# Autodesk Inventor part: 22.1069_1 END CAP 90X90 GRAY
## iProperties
Created: 2007-01
Part Number: 22.1069_1 END CAP 90X90 GRAY
Document SubType Name: Modeling
Designer: Andy Moles
Material: ABS Plastic
Density: 1.06 g/cm^3
Mass: 25.5729 g
Surface Area: 170.413 cm^2
Volume: 24.1253 cm^3
Author: Andy Moles
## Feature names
1. Extrusion1
2. Fillet1
3. Fillet2
4. Extrusion2
5. Fillet3
6. Mirror1
